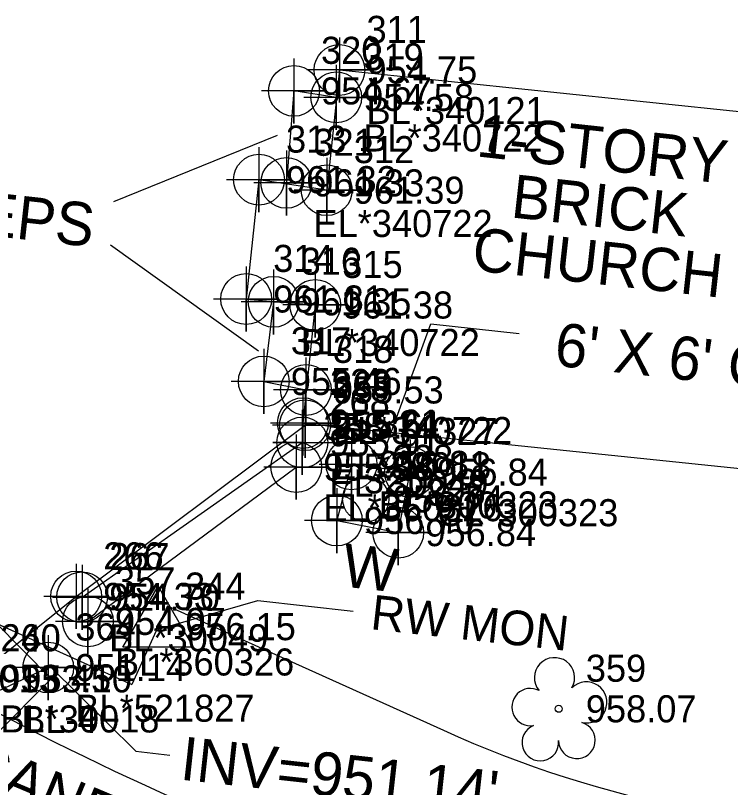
# Model space of a CAD drawing. Extents: x 1150279 to 1151282, y 655434 to 657999.
# Drawn here: x 1150933.3 to 1150999.3, y 657096 to 657167.3 of the extents above; entities that cross this region are included whole.
import ezdxf

# ---------------------------------------------------------------- set-up
doc = ezdxf.new("R2010")
doc.units = 0
for name, color, linetype in [('CTL Supplemental Horizontal and Vertical CELL', 7, 'Continuous'), ('CTL Supplemental Horizontal and Vertical Cogo Comment', 7, 'Continuous'), ('CTL Supplemental Horizontal and Vertical Cogo Elevation', 7, 'Continuous'), ('CTL Supplemental Horizontal and Vertical Cogo Number', 7, 'Continuous'), ('Exist Building', 7, 'Continuous'), ('Exist Building Cogo Elevation', 7, 'Continuous'), ('Exist Building Cogo Number', 7, 'Continuous'), ('Exist Building Cogo Point CELL', 7, 'Continuous'), ('Exist Building Leader', 7, 'Continuous'), ('Exist Building Steps', 7, 'Continuous'), ('Exist Building Steps Cogo Comment', 7, 'Continuous'), ('Exist Building Steps Cogo Elevation', 7, 'Continuous'), ('Exist Building Steps Cogo Number', 7, 'Continuous'), ('Exist Building Steps Cogo Point CELL', 7, 'Continuous'), ('Exist Building Text', 7, 'Continuous'), ('Exist Other Culture Well CELL', 7, 'Continuous'), ('Exist Other Culture Well Cogo Elevation', 7, 'Continuous'), ('Exist Other Culture Well Cogo Number', 7, 'Continuous'), ('Exist Other Culture Well Text', 7, 'Continuous'), ('Exist Right of Way Line', 7, 'Continuous'), ('Exist Right of Way Monument CELL', 7, 'Continuous'), ('Exist Right of Way Monument Cogo Elevation', 7, 'Continuous'), ('Exist Right of Way Monument Cogo Number', 7, 'Continuous'), ('Exist Right of Way Monument Leader', 7, 'Continuous'), ('Exist Right of Way Monument Text', 7, 'Continuous'), ('Exist Roads Curbs', 7, 'Continuous'), ('Exist Roads Curbs Cogo Comment', 7, 'Continuous'), ('Exist Roads Curbs Cogo Elevation', 7, 'Continuous'), ('Exist Roads Curbs Cogo Number', 7, 'Continuous'), ('Exist Roads Curbs Cogo Point CELL', 7, 'Continuous'), ('Exist Roads EOP', 7, 'Continuous'), ('Exist Roads EOP Cogo Comment', 7, 'Continuous'), ('Exist Roads EOP Cogo Elevation', 7, 'Continuous'), ('Exist Roads EOP Cogo Number', 7, 'Continuous'), ('Exist Roads EOP Cogo Point CELL', 7, 'Continuous'), ('Exist Roads EOP Leader', 7, 'Continuous'), ('Exist Roads EOP Other', 7, 'Continuous'), ('Exist Roads EOP Other Cogo Comment', 7, 'Continuous'), ('Exist Roads EOP Other Cogo Elevation', 7, 'Continuous'), ('Exist Roads EOP Other Cogo Number', 7, 'Continuous'), ('Exist Roads EOP Other Cogo Point CELL', 7, 'Continuous'), ('Exist Roads EOP Text', 7, 'Continuous'), ('Exist Structure Minor Pipes CMP 15 Inch Leader', 7, 'Continuous'), ('Exist Structure Minor Pipes CMP 15 Inch Text', 7, 'Continuous'), ('Exist Structure Minor Pipes CMP 18 Inch', 7, 'Continuous'), ('Exist Structure Minor Pipes CMP 18 Inch Cogo Comment', 7, 'Continuous'), ('Exist Structure Minor Pipes CMP 18 Inch Cogo Elevation', 7, 'Continuous'), ('Exist Structure Minor Pipes CMP 18 Inch Cogo Number', 7, 'Continuous'), ('Exist Structure Minor Pipes CMP 18 Inch Cogo Point CELL', 7, 'Continuous'), ('Exist Vegetation Hedge Row', 7, 'Continuous'), ('Exist Vegetation Hedge Row Cogo Comment', 7, 'Continuous'), ('Exist Vegetation Hedge Row Cogo Elevation', 7, 'Continuous'), ('Exist Vegetation Hedge Row Cogo Number', 7, 'Continuous'), ('Exist Vegetation Hedge Row Cogo Point CELL', 7, 'Continuous'), ('Exist Vegetation Tree CELL', 7, 'Continuous'), ('Exist Vegetation Tree Cogo Elevation', 7, 'Continuous'), ('Exist Vegetation Tree Cogo Number', 7, 'Continuous')]:
    doc.layers.add(name, color=color, linetype=linetype)

msp = doc.modelspace()

# ---------------------------------------------------------------- linework, layer by layer
at = {"layer": 'CTL Supplemental Horizontal and Vertical CELL'}
msp.add_lwpolyline([(1150926.077, 657106.08), (1150931.318, 657111.321), (1150936.569, 657106.071), (1150931.327, 657100.83)], close=True, dxfattribs=at)
at = {"layer": 'Exist Building'}
msp.add_line((1150963.173, 657162.304), (1151006.823, 657157.78), dxfattribs=at)
msp.add_lwpolyline([(1150963.173, 657162.304), (1150961.996, 657151.199), (1150955.742, 657152.172), (1150954.56, 657141.15), (1150960.937, 657140.596), (1150959.8, 657129.688), (1151003.45, 657125.164), (1151002.473, 657115.197), (1151037.798, 657111.576), (1151043.235, 657164.115)], dxfattribs=at)
at = {"layer": 'Exist Building Cogo Point CELL'}
for points in [[(1150963.173, 657165.304), (1150963.173, 657159.304), (1150963.173, 657162.304), (1150966.173, 657162.304), (1150960.173, 657162.304)], [(1150955.742, 657155.172), (1150955.742, 657149.172), (1150955.742, 657152.172), (1150958.742, 657152.172), (1150952.742, 657152.172)], [(1150961.996, 657154.199), (1150961.996, 657148.199), (1150961.996, 657151.199), (1150964.996, 657151.199), (1150958.996, 657151.199)], [(1150954.56, 657144.15), (1150954.56, 657138.15), (1150954.56, 657141.15), (1150957.56, 657141.15), (1150951.56, 657141.15)], [(1150960.937, 657143.596), (1150960.937, 657137.596), (1150960.937, 657140.596), (1150963.937, 657140.596), (1150957.937, 657140.596)], [(1150959.8, 657132.688), (1150959.8, 657126.688), (1150959.8, 657129.688), (1150962.8, 657129.688), (1150956.8, 657129.688)]]:
    msp.add_lwpolyline(points, dxfattribs=at)
for centre in [(1150963.173, 657162.304), (1150955.742, 657152.172), (1150961.996, 657151.199), (1150954.56, 657141.15), (1150960.937, 657140.596), (1150959.8, 657129.688)]:
    msp.add_circle(centre, 2.344, dxfattribs=at)
at = {"layer": 'Exist Building Leader'}
for p, q in [((1150957.415, 657156.247), (1150942.315, 657150.133)), ((1150955.698, 657136.327), (1150942.032, 657146.11))]:
    msp.add_line(p, q, dxfattribs=at)
at = {"layer": 'Exist Building Steps'}
for points in [[(1150962.878, 657159.774), (1150958.975, 657160.37), (1150958.272, 657151.876)], [(1150957.09, 657140.886), (1150956.186, 657133.538), (1150960.076, 657132.748)]]:
    msp.add_lwpolyline(points, dxfattribs=at)
at = {"layer": 'Exist Building Steps Cogo Point CELL'}
for points in [[(1150958.975, 657163.37), (1150958.975, 657157.37), (1150958.975, 657160.37), (1150961.975, 657160.37), (1150955.975, 657160.37)], [(1150962.878, 657162.774), (1150962.878, 657156.774), (1150962.878, 657159.774), (1150965.878, 657159.774), (1150959.878, 657159.774)], [(1150958.272, 657154.876), (1150958.272, 657148.876), (1150958.272, 657151.876), (1150961.272, 657151.876), (1150955.272, 657151.876)], [(1150957.09, 657143.886), (1150957.09, 657137.886), (1150957.09, 657140.886), (1150960.09, 657140.886), (1150954.09, 657140.886)], [(1150956.186, 657136.538), (1150956.186, 657130.538), (1150956.186, 657133.538), (1150959.186, 657133.538), (1150953.186, 657133.538)], [(1150960.076, 657135.748), (1150960.076, 657129.748), (1150960.076, 657132.748), (1150963.076, 657132.748), (1150957.076, 657132.748)]]:
    msp.add_lwpolyline(points, dxfattribs=at)
for centre in [(1150958.975, 657160.37), (1150962.878, 657159.774), (1150958.272, 657151.876), (1150957.09, 657140.886), (1150956.186, 657133.538), (1150960.076, 657132.748)]:
    msp.add_circle(centre, 2.344, dxfattribs=at)
at = {"layer": 'Exist Other Culture Well CELL'}
msp.add_circle((1150965.603, 657122.692), 2.132, dxfattribs=at)
at = {"layer": 'Exist Right of Way Line'}
for p, q in [((1150882.786, 657133.198), (1150944.003, 657105.532)), ((1150947.298, 657112.822), (1150944.003, 657105.532)), ((1150947.298, 657112.822), (1150972.772, 657101.31))]:
    msp.add_line(p, q, dxfattribs=at)
msp.add_arc((1151016.013, 657196.992), 105, 245.68044, 271.91872, dxfattribs=at)
at = {"layer": 'Exist Right of Way Monument CELL'}
msp.add_line((1150946.422, 657110.885), (1150946.422, 657110.885), dxfattribs=at)
msp.add_lwpolyline([(1150943.173, 657108.997), (1150946.423, 657114.635), (1150949.67, 657108.996)], close=True, dxfattribs=at)
at = {"layer": 'Exist Right of Way Monument Leader'}
msp.add_lwpolyline([(1150946.455, 657110.649), (1150955.645, 657113.292), (1150964.436, 657112.319)], dxfattribs=at)
at = {"layer": 'Exist Roads Curbs'}
msp.add_line((1150939.414, 657113.606), (1150959.746, 657127.905), dxfattribs=at)
at = {"layer": 'Exist Roads Curbs Cogo Point CELL'}
for points in [[(1150959.746, 657130.905), (1150959.746, 657124.905), (1150959.746, 657127.905), (1150957.016, 657127.905), (1150962.746, 657127.905)], [(1150939.414, 657116.606), (1150939.414, 657110.606), (1150939.414, 657113.606), (1150936.684, 657113.606), (1150942.414, 657113.606)]]:
    msp.add_lwpolyline(points, dxfattribs=at)
for centre in [(1150959.746, 657127.905), (1150939.414, 657113.606)]:
    msp.add_circle(centre, 2.344, dxfattribs=at)
at = {"layer": 'Exist Roads EOP'}
msp.add_lwpolyline([(1150929.365, 657106.111), (1150938.865, 657113.677), (1150959.994, 657129.491)], dxfattribs=at)
msp.add_spline([(1151056.232, 657077.091), (1151010.245, 657076.049), (1150965.316, 657087.792), (1150920.52, 657109.03), (1150919.164, 657109.821)], degree=3, dxfattribs=at)
at = {"layer": 'Exist Roads EOP Cogo Point CELL'}
for points in [[(1150959.994, 657132.491), (1150959.994, 657126.491), (1150959.994, 657129.491), (1150962.994, 657129.491), (1150956.994, 657129.491)], [(1150938.865, 657116.677), (1150938.865, 657110.677), (1150938.865, 657113.677), (1150941.865, 657113.677), (1150935.865, 657113.677)]]:
    msp.add_lwpolyline(points, dxfattribs=at)
for centre in [(1150959.994, 657129.491), (1150938.865, 657113.677)]:
    msp.add_circle(centre, 2.344, dxfattribs=at)
at = {"layer": 'Exist Roads EOP Leader'}
msp.add_lwpolyline([(1150966.81, 657125.701), (1150971.617, 657138.864), (1150979.775, 657137.961)], dxfattribs=at)
at = {"layer": 'Exist Roads EOP Other'}
msp.add_lwpolyline([(1150964.287, 657125.875), (1150962.937, 657120.687), (1150968.604, 657119.571), (1150969.691, 657125.162), (1150964.287, 657125.875)], dxfattribs=at)
at = {"layer": 'Exist Roads EOP Other Cogo Point CELL'}
for points in [[(1150964.287, 657128.875), (1150964.287, 657122.875), (1150964.287, 657125.875), (1150967.287, 657125.875), (1150961.287, 657125.875)], [(1150969.691, 657128.162), (1150969.691, 657122.162), (1150969.691, 657125.162), (1150972.691, 657125.162), (1150966.691, 657125.162)], [(1150962.937, 657123.687), (1150962.937, 657117.687), (1150962.937, 657120.687), (1150965.937, 657120.687), (1150959.937, 657120.687)], [(1150968.604, 657122.571), (1150968.604, 657116.571), (1150968.604, 657119.571), (1150971.604, 657119.571), (1150965.604, 657119.571)]]:
    msp.add_lwpolyline(points, dxfattribs=at)
for centre in [(1150964.287, 657125.875), (1150969.691, 657125.162), (1150962.937, 657120.687), (1150968.604, 657119.571)]:
    msp.add_circle(centre, 2.344, dxfattribs=at)
at = {"layer": 'Exist Structure Minor Pipes CMP 15 Inch Leader'}
msp.add_lwpolyline([(1150936.514, 657107.147), (1150944.362, 657099.378), (1150947.527, 657099.028)], dxfattribs=at)
at = {"layer": 'Exist Structure Minor Pipes CMP 18 Inch'}
msp.add_line((1150936.288, 657107.106), (1150895.921, 657088.095), dxfattribs=at)
at = {"layer": 'Exist Structure Minor Pipes CMP 18 Inch Cogo Point CELL'}
msp.add_lwpolyline([(1150936.288, 657110.106), (1150936.288, 657104.106), (1150936.288, 657107.106), (1150939.288, 657107.106), (1150933.288, 657107.106)], dxfattribs=at)
msp.add_circle((1150936.288, 657107.106), 2.344, dxfattribs=at)
at = {"layer": 'Exist Vegetation Hedge Row'}
msp.add_line((1150939.948, 657111.372), (1150959.188, 657125.623), dxfattribs=at)
at = {"layer": 'Exist Vegetation Hedge Row Cogo Point CELL'}
for points in [[(1150959.188, 657128.623), (1150959.188, 657122.623), (1150959.188, 657125.623), (1150962.188, 657125.623), (1150956.188, 657125.623)], [(1150939.948, 657114.372), (1150939.948, 657108.372), (1150939.948, 657111.372), (1150942.948, 657111.372), (1150936.948, 657111.372)]]:
    msp.add_lwpolyline(points, dxfattribs=at)
for centre in [(1150959.188, 657125.623), (1150939.948, 657111.372)]:
    msp.add_circle(centre, 2.344, dxfattribs=at)
at = {"layer": 'Exist Vegetation Tree CELL'}
msp.add_line((1150983.421, 657103.298), (1150983.421, 657103.298), dxfattribs=at)
msp.add_circle((1150983.421, 657103.298), 0.326, dxfattribs=at)
for centre, radius, start, end in [((1150983.036, 657106.171), 1.856, 330.16508, 219.71335), ((1150985.97, 657103.886), 1.899, 257.1011, 134.19993), ((1150980.815, 657103.452), 1.727, 62.66361, 279.3457), ((1150981.717, 657100.177), 1.689, 111.56708, 6.23104), ((1150985.094, 657100.398), 1.698, 181.28216, 74.55999)]:
    msp.add_arc(centre, radius, start, end, dxfattribs=at)

# ---------------------------------------------------------------- texts
at = {"layer": 'CTL Supplemental Horizontal and Vertical Cogo Comment'}
msp.add_text('BL-4', height=2.5, dxfattribs=at).set_placement((1150933.792, 657101.062))
at = {"layer": 'CTL Supplemental Horizontal and Vertical Cogo Elevation'}
msp.add_text('953.10', height=2.5, dxfattribs=at).set_placement((1150933.792, 657104.812))
at = {"layer": 'CTL Supplemental Horizontal and Vertical Cogo Number'}
msp.add_text('4', height=2.5, dxfattribs=at).set_placement((1150933.792, 657108.562))
at = {"layer": 'Exist Building Cogo Elevation'}
for s, p in [('954.75', (1150965.673, 657161.054)), ('BL*340121', (1150965.673, 657157.304)), ('961.32', (1150958.242, 657150.922)), ('961.39', (1150964.496, 657149.949)), ('961.31', (1150957.06, 657139.9)), ('961.38', (1150963.437, 657139.346)), ('955.61', (1150962.3, 657128.438))]:
    msp.add_text(s, height=2.5, dxfattribs=at).set_placement(p)
at = {"layer": 'Exist Building Cogo Number'}
for s, p in [('311', (1150965.673, 657164.804)), ('313', (1150958.242, 657154.672)), ('312', (1150964.496, 657153.699)), ('314', (1150957.06, 657143.65)), ('315', (1150963.437, 657143.096)), ('323', (1150962.3, 657132.188))]:
    msp.add_text(s, height=2.5, dxfattribs=at).set_placement(p)
at = {"layer": 'Exist Building Steps Cogo Comment'}
for s, p in [('BL*340722', (1150965.378, 657154.774)), ('EL*340722', (1150960.772, 657146.876)), ('BL*340722', (1150959.59, 657135.886)), ('EL*340722', (1150962.576, 657127.748))]:
    msp.add_text(s, height=2.5, dxfattribs=at).set_placement(p)
at = {"layer": 'Exist Building Steps Cogo Elevation'}
for s, p in [('954.67', (1150961.475, 657159.12)), ('954.58', (1150965.378, 657158.524)), ('961.33', (1150960.772, 657150.626)), ('961.35', (1150959.59, 657139.636)), ('955.46', (1150958.686, 657132.288)), ('955.53', (1150962.576, 657131.498))]:
    msp.add_text(s, height=2.5, dxfattribs=at).set_placement(p)
at = {"layer": 'Exist Building Steps Cogo Number'}
for s, p in [('320', (1150961.475, 657162.87)), ('319', (1150965.378, 657162.274)), ('321', (1150960.772, 657154.376)), ('316', (1150959.59, 657143.386)), ('317', (1150958.686, 657136.038)), ('318', (1150962.576, 657135.248))]:
    msp.add_text(s, height=2.5, dxfattribs=at).set_placement(p)
at = {"layer": 'Exist Building Text'}
for s, p in [('1-STORY', (1150975.737, 657154.333)), ('BRICK', (1150978.916, 657148.699)), ('STEPS', (1150922.885, 657147.878)), ('CHURCH', (1150975.302, 657143.817))]:
    msp.add_text(s, height=4, rotation=353.6867, dxfattribs=at).set_placement(p)
at = {"layer": 'Exist Other Culture Well Cogo Elevation'}
msp.add_text('956.74', height=2.5, dxfattribs=at).set_placement((1150968.099, 657121.438))
at = {"layer": 'Exist Other Culture Well Cogo Number'}
msp.add_text('328', height=2.5, dxfattribs=at).set_placement((1150968.099, 657125.188))
at = {"layer": 'Exist Other Culture Well Text'}
msp.add_text('W', height=4, rotation=353.6867, dxfattribs=at).set_placement((1150963.294, 657114.609))
at = {"layer": 'Exist Right of Way Monument Cogo Elevation'}
msp.add_text('956.15', height=2.5, dxfattribs=at).set_placement((1150948.922, 657109.635))
at = {"layer": 'Exist Right of Way Monument Cogo Number'}
msp.add_text('344', height=2.5, dxfattribs=at).set_placement((1150948.922, 657113.385))
at = {"layer": 'Exist Right of Way Monument Text'}
msp.add_text('RW MON', height=3.2, rotation=353.6867, dxfattribs=at).set_placement((1150965.97, 657110.662))
at = {"layer": 'Exist Roads Curbs Cogo Comment'}
for s, p in [('EL*30049', (1150962.246, 657122.905)), ('BL*30049', (1150941.914, 657108.606))]:
    msp.add_text(s, height=2.5, dxfattribs=at).set_placement(p)
at = {"layer": 'Exist Roads Curbs Cogo Elevation'}
for s, p in [('955.91', (1150962.246, 657126.655)), ('954.70', (1150941.914, 657112.356))]:
    msp.add_text(s, height=2.5, dxfattribs=at).set_placement(p)
at = {"layer": 'Exist Roads Curbs Cogo Number'}
for s, p in [('268', (1150962.246, 657130.405)), ('267', (1150941.914, 657116.106))]:
    msp.add_text(s, height=2.5, dxfattribs=at).set_placement(p)
at = {"layer": 'Exist Roads EOP Cogo Comment'}
for s, p in [('EL*30018', (1150962.494, 657124.491)), ('OC*30013', (1150921.664, 657104.821)), ('BL*30018', (1150931.865, 657101.111))]:
    msp.add_text(s, height=2.5, dxfattribs=at).set_placement(p)
at = {"layer": 'Exist Roads EOP Cogo Elevation'}
for s, p in [('955.61', (1150962.494, 657128.241)), ('954.33', (1150941.365, 657112.427)), ('953.45', (1150931.865, 657104.861))]:
    msp.add_text(s, height=2.5, dxfattribs=at).set_placement(p)
at = {"layer": 'Exist Roads EOP Cogo Number'}
for s, p in [('269', (1150962.494, 657131.991)), ('266', (1150941.365, 657116.177)), ('260', (1150931.865, 657108.611))]:
    msp.add_text(s, height=2.5, dxfattribs=at).set_placement(p)
at = {"layer": 'Exist Roads EOP Other Cogo Comment'}
for s, p in [('BL*300323', (1150966.787, 657120.875)), ('CL*300323', (1150972.191, 657120.162))]:
    msp.add_text(s, height=2.5, dxfattribs=at).set_placement(p)
at = {"layer": 'Exist Roads EOP Other Cogo Elevation'}
for s, p in [('956.81', (1150966.787, 657124.625)), ('956.84', (1150972.191, 657123.912)), ('956.70', (1150965.437, 657119.437)), ('956.84', (1150971.104, 657118.321))]:
    msp.add_text(s, height=2.5, dxfattribs=at).set_placement(p)
at = {"layer": 'Exist Roads EOP Other Cogo Number'}
for s, p in [('324', (1150966.787, 657128.375)), ('327', (1150972.191, 657127.662)), ('325', (1150965.437, 657123.187)), ('326', (1150971.104, 657122.071))]:
    msp.add_text(s, height=2.5, dxfattribs=at).set_placement(p)
at = {"layer": 'Exist Roads EOP Text'}
for s, rotation, p in [("6' X 6' CONC. PAD", 353.6867, (1150982.918, 657135.017)), ('CANE CREEK MTN. RD.', 337.10646, (1150928.179, 657096.94))]:
    msp.add_text(s, height=4, rotation=rotation, dxfattribs=at).set_placement(p)
at = {"layer": 'Exist Structure Minor Pipes CMP 15 Inch Text'}
msp.add_text("INV=951.14'", height=4, rotation=353.6867, dxfattribs=at).set_placement((1150948.372, 657096.768))
at = {"layer": 'Exist Structure Minor Pipes CMP 18 Inch Cogo Comment'}
msp.add_text('BL*521827', height=2.5, dxfattribs=at).set_placement((1150938.788, 657102.106))
at = {"layer": 'Exist Structure Minor Pipes CMP 18 Inch Cogo Elevation'}
msp.add_text('951.14', height=2.5, dxfattribs=at).set_placement((1150938.788, 657105.856))
at = {"layer": 'Exist Structure Minor Pipes CMP 18 Inch Cogo Number'}
msp.add_text('364', height=2.5, dxfattribs=at).set_placement((1150938.788, 657109.606))
at = {"layer": 'Exist Vegetation Hedge Row Cogo Comment'}
for s, p in [('EL*360326', (1150961.688, 657120.623)), ('BL*360326', (1150942.448, 657106.372))]:
    msp.add_text(s, height=2.5, dxfattribs=at).set_placement(p)
at = {"layer": 'Exist Vegetation Hedge Row Cogo Elevation'}
for s, p in [('955.98', (1150961.688, 657124.373)), ('954.07', (1150942.448, 657110.122))]:
    msp.add_text(s, height=2.5, dxfattribs=at).set_placement(p)
at = {"layer": 'Exist Vegetation Hedge Row Cogo Number'}
for s, p in [('358', (1150961.688, 657128.123)), ('357', (1150942.448, 657113.872))]:
    msp.add_text(s, height=2.5, dxfattribs=at).set_placement(p)
at = {"layer": 'Exist Vegetation Tree Cogo Elevation'}
msp.add_text('958.07', height=2.5, dxfattribs=at).set_placement((1150985.921, 657102.048))
at = {"layer": 'Exist Vegetation Tree Cogo Number'}
msp.add_text('359', height=2.5, dxfattribs=at).set_placement((1150985.921, 657105.798))

doc.saveas('drawing.dxf')
